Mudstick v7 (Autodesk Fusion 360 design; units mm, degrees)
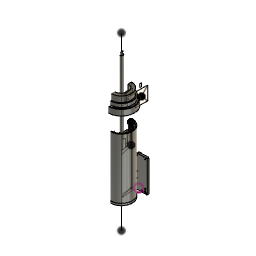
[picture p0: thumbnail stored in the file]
parameter "flexure_w" = 1.5
parameter "gap_w" = 1
parameter "t_sheet_main" = 6.6
parameter "t_sheet_second" = 3.175 (= "1 / 8 * 1")
parameter "tube_wallthick" = 3.3
parameter "tube_id" = 70
parameter "tube_len" = 210
parameter "id_bspushbearing" = 40
parameter "od_bspushbearing" = 52
parameter "t_bspushbearing" = 7
parameter "hw_m4insert_d" = 5.8
parameter "hw_m4insert_l" = 4.6
parameter "p_teeth" = 2
parameter "pd_pinion" = 12.7324 (= "p_teeth * nt_pinion / PI")
parameter "pd_driven" = 76.3944 (= "p_teeth * nt_driven / PI")
parameter "belt_length" = 280
parameter "c_dist_manuel" = 70.75
parameter "d101" = 7 (= "t_bspushbearing")
sketch "Sketch1" plane through (0, 0, 0) normal (0, 1, 0) x axis (1, 0, 0)
  line L1 (73.8, 0) -> (0, 0)
  line L2 (73.8, -110) -> (73.8, 0)
  line L3 (0, -110) -> (73.8, -110)
  line L4 (0, 0) -> (0, -110)
  line L5 (36.9, 0) -> (36.9, -110)
  line L6 (34.4, -109) -> (36.9, -109)
  line L7 (34.4, -101) -> (34.4, -109)
  line L8 (36.9, -101) -> (34.4, -101)
  line L9 (36.9, -45) -> (6.9, -5)
  line L10 (2.5, -3.3) -> (7.3, -9.7)
  line L11 (6.5, -0.3) -> (2.5, -3.3)
  line L12 (11.3, -6.7) -> (6.5, -0.3)
  line L13 (7.3, -9.7) -> (11.3, -6.7)
  line L14 (6.9, -5) -> (4.9, -6.5)
  circle C1 centre (6.9, -105) radius 2.1
  circle C2 centre (6.9, -15) radius 2.1
  circle C3 centre (16.9, -5) radius 2.1
  circle C4 centre (36.9, -55) radius 2.1
  circle C5 centre (36.9, -35) radius 2.1
  circle C6 centre (36.9, -45) radius 35.125
  circle C7 centre (6.9, -15) radius 4.1
  circle C8 centre (6.9, -105) radius 4.1
  circle C9 centre (16.9, -5) radius 4.1
  circle C10 centre (36.9, -55) radius 4.1
  circle C11 centre (36.9, -35) radius 4.1
  point P1 (0, 0)
  point P2 (0, 0)
  point P6 (36.9, -110)
  point P7 (36.9, 0)
  point P11 (36.9, -55)
  point P12 (36.9, -35)
  point P13 (36.9, -45)
  point P14 (36.9, -45)
  point P15 (36.9, -109)
  point P18 (36.9, -101)
  point P19 (34.4, -105)
  point P8 (6.9, -105)
  point P21 (36.9, -45)
  point P9 (6.9, -15)
  point P20 (6.9, -5)
  point P10 (16.9, -5)
  point P26 (9.3, -8.2)
  point P27 (4.9, -6.5)
  point P28 (6.9, -5)
  point P4 (73.8, -110)
  point P5 (0, -110)
  point P16 (34.4, -109)
  point P17 (34.4, -101)
  point P22 (7.3, -9.7)
  point P25 (11.3, -6.7)
  point P24 (6.5, -0.3)
  point P33 (36.9, -35)
  point P30 (6.9, -105)
  horizontal L1
  vertical L2
  horizontal L3
  coincident P1 P2
  midpoint L3 P6
  midpoint L1 P7
  equal C1 C2
  equal C1 C3
  coincident L5 P11
  coincident L5 P12
  equal C1 C4
  equal C1 C5
  coincident L5 P13
  coincident P13 P14
  coincident L5 P15
  perpendicular L5 L6
  perpendicular L6 L7
  perpendicular L5 L8
  coincident L5 P18
  midpoint L7 P19
  horizontal P8 P19
  coincident P14 P21
  vertical P9 P20
  horizontal P10 P20
  perpendicular L10 L11
  parallel L10 L12
  parallel L11 L13
  midpoint L13 P26
  coincident L9 P26
  midpoint L10 P27
  perpendicular L10 L14
  coincident P20 P28
  concentric C2 C7
  vertical L4
  perpendicular L9 L14
  concentric C1 C8
  concentric C3 C9
  equal C7 C9
  equal C7 C8
  concentric C4 C10
  concentric C5 C11
  equal C8 C10
  equal C8 C11
  dimension "d1" distance P4 P5 = 73.8
  dimension "d2" distance P2 P5 = 110
  dimension "d3" distance L5 P8 = 30
  dimension "d4" distance L3 P8 = 5
  dimension "d5" diameter C1 = 4.2
  dimension "d6" distance P11 P12 = 20
  dimension "d7" distance P8 P11 = 50
  dimension "d8" distance L1 P9 = 15
  dimension "d9" distance L1 P10 = 5
  dimension "d10" distance L5 P10 = 20
  dimension "d11" distance L5 P9 = 30
  dimension "d12" distance P12 P13 = 10
  dimension "d13" diameter C6 = 70.25
  dimension "d14" distance P15 P16 = 2.5
  dimension "d15" distance P16 P17 = 8
  dimension "d16" distance P22 P25 = 5
  dimension "d17" distance P24 P25 = 8
  dimension "d25" diameter C7 = 8.2
  dimension "d61" distance P10 P33 = 30
  dimension "d62" distance P9 P33 = 20
  dimension "d63" distance P30 P33 = 70
  dimension "d64" distance P8 P9 = 90
extrude "Extrude3" new body sketch "Sketch1" profile of L1 L3 L4 L5 C1 C2 C3 C4 C5 L6 L7 L8 L10 L11 L12 L13 C7 C8 C9 C10 C11 no distance stored bodies "Home Plate"
fillet "Fillet11" radius 1
mirror "Mirror3"
combine "Combine2"
work_plane "WorkPlane1"
sketch "Revolve" plane through (36.9, -3.3, 55) normal (-1, 0, 0) x axis (0, 1, 0)
  line L1 (-21.7, 45) -> (-18.4, 45)
  line L2 (-21.7, -165) -> (-21.7, 45)
  line L3 (-56.7, 45) -> (-21.7, 45)
  line L4 (-56.7, -445) -> (-56.7, 155)
  line L5 (-18.4, -165) -> (-18.4, 45)
  line L6 (-21.7, -165) -> (-18.4, -165)
  line L7 (-21.75, 45.05) -> (-18.4, 45.05)
  line L8 (-21.75, 40.05) -> (-21.75, 45.05)
  line L9 (-22.75, 40.05) -> (-21.75, 40.05)
  line L10 (-53.2, 51.1329) -> (-22.75, 40.05)
  line L11 (-53.2, 55.1329) -> (-53.2, 51.1329)
  line L12 (-18.4, 45.05) -> (-18.4, 52.0883)
  line L13 (-18.4, 52.0883) -> (-53.2, 55.1329)
  line L14 (-56.7, -75.8671) -> (-22.2, -85.1114)
  line L15 (-11.08, -225) -> (-30.7, -225)
  line L16 (-30.7, -230) -> (-30.7, -225)
  line L17 (-33.7, -233) -> (-30.7, -230)
  line L18 (-33.7, -237) -> (-33.7, -233)
  line L19 (-30.7, -240) -> (-33.7, -237)
  line L20 (-30.7, -245) -> (-30.7, -240)
  line L21 (-11.08, -245) -> (-30.7, -245)
  line L22 (-25.62, -238.4) -> (-25.62, -245)
  line L23 (-13.62, -238.4) -> (-25.62, -238.4)
  line L24 (-13.62, -245) -> (-13.62, -238.4)
  line L25 (-11.08, -225) -> (-11.08, -245)
  line L26 (-36.7, -243.7) -> (-35.4, -245)
  line L27 (-36.7, -229) -> (-36.7, -243.7)
  line L28 (-45.45, -229) -> (-36.7, -229)
  line L29 (-45.45, -258.5) -> (-45.45, -229)
  line L30 (-36.7, -226.3) -> (-36.7, -228.5)
  line L31 (-35.4, -225) -> (-36.7, -226.3)
  line L32 (-34.7, -225) -> (-35.4, -225)
  line L33 (-34.7, -222) -> (-34.7, -225)
  line L34 (-45.45, -222) -> (-34.7, -222)
  line L35 (-45.45, -228.5) -> (-45.45, -222)
  line L36 (-36.7, -228.5) -> (-45.45, -228.5)
  line L37 (-34.7, -245) -> (-35.4, -245)
  line L38 (-34.7, -246.5) -> (-34.7, -245)
  line L39 (-40.7, -258.5) -> (-40.7, -229)
  line L40 (-42.85, -236.35) -> (-42.85, -253.15)
  line L41 (-38.55, -258.5) -> (-38.55, -229)
  line L42 (-17.5028, -258.5) -> (-45.45, -258.5)
  line L43 (-40.7, -222) -> (-40.7, -228.5)
  line L44 (-42.85, -228.5) -> (-42.85, -222)
  line L45 (-17.5028, -246.5) -> (-34.7, -246.5)
  line L46 (-17.5028, -258.5) -> (-17.5028, -246.5)
  line L47 (-36.7, -232) -> (-32.7, -232)
  line L48 (7.6838, -246.5) -> (7.6838, -258.5)
  line L49 (14.05, -246.5) -> (7.6838, -246.5)
  line L50 (14.05, -258.5) -> (14.05, -246.5)
  line L51 (7.6838, -258.5) -> (14.05, -258.5)
  line L52 (35.2, -193) -> (-7.1, -193)
  line L53 (35.2, -241) -> (35.2, -193)
  line L54 (-7.1, -241) -> (35.2, -241)
  line L55 (-7.1, -193) -> (-7.1, -241)
  line L56 (35.2, -241) -> (-7.1, -193)
  line L57 (-7.1, -241) -> (35.2, -193)
  line L58 (-52.7, -89.8671) -> (-56.7, -89.8671)
  line L59 (-52.7, -104.8671) -> (-52.7, -89.8671)
  line L60 (-51.7, -104.8671) -> (-52.7, -104.8671)
  line L61 (-51.7, -143.8671) -> (-51.7, -104.8671)
  line L62 (-50.7, -143.8671) -> (-51.7, -143.8671)
  line L63 (-50.7, -379.8671) -> (-50.7, -143.8671)
  line L64 (-52.7, -379.8671) -> (-50.7, -379.8671)
  line L65 (-52.7, -389.8671) -> (-52.7, -379.8671)
  line L66 (-56.7, -389.8671) -> (-52.7, -389.8671)
  line L67 (-21.5028, -278.5) -> (-21.5028, -258.5)
  line L68 (-33.5028, -278.5) -> (-21.5028, -278.5)
  line L69 (-33.5028, -258.5) -> (-33.5028, -278.5)
  line L70 (-26.24, -104.7344) -> (-26.24, -160.8276)
  line L71 (-35.7725, -102.1801) -> (-26.24, -104.7344)
  line L72 (-36.7, -91.5789) -> (-35.7725, -102.1801)
  line L73 (-56.7, -86.2199) -> (-36.7, -91.5789)
  line L74 (-26.24, -160.8276) -> (-22.2, -160.8276)
  line L75 (-30.6415, -160.8276) -> (-35.7725, -102.1801)
  line L76 (-26.24, -160.8276) -> (-30.6415, -160.8276)
  line L77 (-51.45, -141.6671) -> (-51.45, -119.0671)
  line L78 (-35.9267, -141.6671) -> (-51.45, -141.6671)
  line L79 (-36.8449, -91.6436) -> (-35.9267, -102.1388)
  line L80 (-42.5953, -90.1027) -> (-36.8449, -91.6436)
  line L81 (-42.5953, -119.0671) -> (-42.5953, -90.1027)
  line L82 (-51.45, -119.0671) -> (-42.5953, -119.0671)
  line L83 (-35.9267, -141.6671) -> (-35.9267, -102.1388)
  line L84 (-42.5953, -100.352) -> (-35.9267, -102.1388)
  line L85 (-35.9267, -102.1388) -> (-35.7725, -102.1801)
  line L86 (-42.5953, -89.9992) -> (-42.5953, -90.1027)
  line L87 (-22.2, -88.8276) -> (-22.8081, -88.8276)
  line L88 (-22.2, -85.1114) -> (-22.2, -86.1114)
  line L89 (-23.7, -92.3276) -> (-22.2, -90.8276)
  line L90 (-23.7, -153.6114) -> (-23.7, -92.3276)
  line L91 (-22.8081, -158.8276) -> (-22.2, -158.8276)
  line L92 (-22.2, -155.1114) -> (-22.2, -156.1114)
  line L93 (-23.7, -153.6114) -> (-22.2, -155.1114)
  line L94 (-22.2, -86.1114) -> (-22.8081, -86.1114)
  line L95 (-22.2, -156.1114) -> (-22.8081, -156.1114)
  line L96 (-22.2, -156.1114) -> (-22.2, -88.8276)
  line L97 (-22.2, -160.8276) -> (-22.2, -156.1114)
  line L98 (-43.6, -253.9) -> (-42.85, -253.15)
  line L99 (-43.6, -258.5) -> (-43.6, -253.9)
  line L100 (-43.6, -235.6) -> (-42.85, -236.35)
  line L101 (-43.6, -229) -> (-43.6, -235.6)
  line L102 (-35.7, -214) -> (-35.7, -222)
  line L103 (-50.7, -214) -> (-35.7, -214)
  circle C1 centre (-22.8081, -87.4695) radius 1.3081
  arc A1 centre (-22.8081, -87.4695) radius 1.3581 clockwise from (-22.8081, -88.8276) to (-22.8081, -86.1114)
  circle C2 centre (-22.8081, -157.4695) radius 1.3081
  arc A2 centre (-22.8081, -157.4695) radius 1.3581 clockwise from (-22.8081, -158.8276) to (-22.8081, -156.1114)
  point P4 (-21.7, -165)
  point P10 (-21.7, -165)
  point P5 (-56.7, 45)
  point P11 (-18.4, 45.05)
  point P18 (-18.4, 45.05)
  point P2 (-18.4, 45)
  point P16 (-53.2, 55.1329)
  point P19 (-53.2, 55.1329)
  point P21 (-56.7, -75.8671)
  point P28 (-30.7, -240)
  point P31 (-25.62, -245)
  point P34 (-13.62, -245)
  point P24 (-11.08, -225)
  point P35 (-11.08, -225)
  point P41 (-36.7, -228.5)
  point P48 (-36.7, -228.5)
  point P39 (-45.45, -229)
  point P51 (-40.7, -229)
  point P53 (-38.55, -229)
  point P23 (-30.7, -225)
  point P52 (-40.7, -258.5)
  point P54 (-38.55, -258.5)
  point P29 (-30.7, -245)
  point P44 (-34.7, -225)
  point P56 (-40.7, -228.5)
  point P57 (-40.7, -222)
  point P59 (-42.85, -228.5)
  point P62 (-32.7, -232)
  point P63 (-36.7, -232)
  point P64 (7.6838, -258.5)
  point P68 (7.6838, -258.5)
  point P73 (14.05, -217)
  point P66 (14.05, -246.5)
  point P61 (-17.5028, -258.5)
  point P60 (-17.5028, -246.5)
  point P74 (-56.7, -89.8671)
  point P83 (-56.7, -389.8671)
  point P92 (-56.7, -86.2199)
  point P88 (-26.24, -160.8276)
  point P93 (-26.24, -160.8276)
  point P94 (-51.45, -119.0671)
  point P99 (-51.45, -119.0671)
  point P101 (-30.6415, -160.8276)
  point P102 (-30.6415, -160.8276)
  point P103 (-35.9267, -102.1388)
  point P105 (-42.5953, -100.352)
  point P100 (-35.9267, -141.6671)
  point P104 (-35.9267, -141.6671)
  point P106 (-42.5953, -89.9992)
  point P108 (-21.5, -87.4695)
  point P107 (-22.8081, -87.4695)
  point P109 (-22.8081, -87.4695)
  point P20 (-22.2, -85.1114)
  point P112 (-22.2, -85.1114)
  point P113 (-22.2, -90.8276)
  point P116 (-22.8081, -157.4695)
  point P117 (-22.2, -158.8276)
  point P119 (-22.8081, -157.4695)
  point P115 (-23.7, -153.6114)
  point P121 (-23.7, -153.6114)
  point P111 (-22.2, -88.8276)
  point P125 (-22.2, -156.1114)
  point P58 (-42.85, -222)
  point P55 (-17.5028, -258.5)
  point P84 (-21.5028, -258.5)
  point P87 (-33.5028, -258.5)
  point P128 (-43.6, -258.5)
  point P131 (-43.6, -229)
  point P129 (-42.85, -236.35)
  point P132 (-35.7, -222)
  point P134 (-50.7, -214)
  point P8 (3.3, 55)
  point P3 (-21.7, 45)
  point P6 (-56.7, 155)
  point P7 (-56.7, -445)
  point P12 (-21.75, 45.05)
  point P13 (-21.75, 40.05)
  point P14 (-22.75, 40.05)
  point P15 (-53.2, 51.1329)
  point P33 (-13.62, -238.4)
  point P32 (-25.62, -238.4)
  point P30 (-11.08, -245)
  point P42 (-36.7, -226.3)
  point P49 (-34.7, -245)
  point P50 (-34.7, -246.5)
  point P45 (-34.7, -222)
  point P37 (-36.7, -243.7)
  point P67 (14.05, -258.5)
  point P71 (35.2, -241)
  point P72 (-7.1, -241)
  point P70 (35.2, -193)
  point P81 (-52.7, -379.8671)
  point P82 (-52.7, -389.8671)
  point P75 (-52.7, -89.8671)
  point P76 (-52.7, -104.8671)
  point P77 (-51.7, -104.8671)
  point P78 (-51.7, -143.8671)
  point P85 (-21.5028, -278.5)
  point P86 (-33.5028, -278.5)
  point P79 (-50.7, -143.8671)
  point P91 (-36.7, -91.5789)
  point P120 (-22.2, -155.1114)
  point P123 (-22.2, -86.1114)
  point P46 (-45.45, -222)
  point P127 (-43.6, -253.9)
  point P130 (-43.6, -235.6)
  point P133 (-35.7, -214)
  horizontal L1
  perpendicular L1 L2
  perpendicular L2 L3
  vertical L4
  perpendicular L3 L5
  perpendicular L5 L6
  coincident P4 P10
  coincident P5 L4
  perpendicular L2 L7
  perpendicular L3 L8
  perpendicular L8 L9
  perpendicular L3 L11
  parallel L11 L12
  coincident P11 P18
  coincident P2 L12
  coincident P16 P19
  coincident L4 P21
  perpendicular L74 L96
  horizontal L15
  perpendicular L15 L16
  perpendicular L15 L18
  perpendicular L17 L19
  perpendicular L18 L21
  vertical L20
  equal L16 L20
  coincident L16 P28
  coincident L21 P31
  perpendicular L21 L22
  perpendicular L22 L23
  coincident L21 P34
  perpendicular L21 L24
  perpendicular L21 L25
  coincident P24 P35
  vertical L27
  perpendicular L27 L28
  perpendicular L28 L29
  perpendicular L28 L30
  perpendicular L30 L32
  perpendicular L32 L33
  perpendicular L33 L34
  perpendicular L34 L35
  perpendicular L35 L36
  coincident P41 P48
  coincident L27 P48
  coincident P39 L35
  horizontal L37
  perpendicular L37 L38
  coincident L28 P51
  perpendicular L28 L39
  perpendicular L28 L40
  coincident L28 P53
  perpendicular L28 L41
  coincident P23 L32
  perpendicular L29 L42
  coincident P52 L42
  coincident P54 L42
  coincident P29 L37
  coincident P44 L38
  coincident L36 P56
  coincident L34 P57
  perpendicular L34 L43
  coincident P51 L43
  coincident L36 P59
  perpendicular L36 L44
  perpendicular L38 L45
  perpendicular L45 L46
  coincident L17 P62
  coincident L27 P63
  perpendicular L27 L47
  vertical L48
  perpendicular L48 L49
  perpendicular L49 L50
  perpendicular L50 L51
  coincident P64 P68
  perpendicular L52 L53
  parallel L52 L54
  parallel L53 L55
  horizontal L52
  coincident L56 P73
  coincident L57 P73
  vertical P66 P73
  coincident P61 L51
  coincident P60 L49
  coincident L4 P74
  perpendicular L4 L58
  perpendicular L58 L59
  perpendicular L4 L60
  perpendicular L60 L61
  perpendicular L4 L62
  perpendicular L62 L63
  perpendicular L63 L64
  perpendicular L64 L65
  coincident L4 P83
  perpendicular L4 L66
  perpendicular L67 L68
  perpendicular L70 L74
  coincident L4 P92
  parallel L71 L73
  parallel L14 L71
  coincident P88 P93
  vertical L77
  perpendicular L78 L81
  coincident P94 P99
  parallel L73 L80
  parallel L72 L75
  coincident P101 P102
  horizontal L76
  parallel L75 L79
  coincident L71 P103
  coincident L81 P105
  collinear L71 L84
  horizontal L82
  coincident P100 P104
  vertical L83
  coincident L73 P106
  parallel L81 L86
  coincident C1 P108
  horizontal P107 P108
  vertical L96
  coincident P107 P109
  horizontal L87
  vertical L88
  coincident P20 P112
  tangent A1 L87
  coincident P113 L96
  vertical L90
  vertical P107 P116
  equal C1 C2
  coincident P117 L96
  perpendicular L91 L96
  coincident P116 P119
  tangent L91 A2
  vertical L92
  coincident P115 P121
  coincident P111 L88
  tangent A1 L94
  horizontal L94
  tangent A2 L95
  coincident L92 P125
  horizontal L95
  collinear L96 L97
  coincident L34 P58
  coincident P55 P61
  vertical L69
  vertical L67
  coincident L42 P84
  coincident L42 P87
  coincident L42 P128
  perpendicular L42 L99
  coincident L28 P131
  perpendicular L28 L101
  coincident L44 P129
  coincident L34 P132
  perpendicular L34 L102
  coincident L63 P134
  perpendicular L63 L103
  dimension "d75" distance L4 P8 = 60
  dimension "d76" distance P2 P3 = 3.3 (= "tube_wallthick")
  dimension "d80" distance L2 L4 = 35 (= "tube_id / 2")
  dimension "d81" distance P3 P4 = 210 (= "tube_len")
  dimension "d82" distance L3 P8 = 10
  dimension "d83" distance P6 P8 = 100
  dimension "d84" distance P7 P8 = 500
  dimension "d85" distance L1 L7 = 0.05
  dimension "d86" distance P12 P13 = 5
  dimension "d87" distance L2 L8 = 0.05
  dimension "d88" distance P13 P14 = 1
  dimension "d89" angle L10 L11 = 70
  dimension "d90" distance P15 P16 = 4
  dimension "d92" angle L11 L13 = 85
  dimension "d93" distance L4 L11 = 3.5
  dimension "d96" angle L10 L14 = 5
  dimension "d103" angle L18 L19 = 45
  dimension "d105" distance P28 P29 = 5
  dimension "d106" distance L4 L20 = 26 (= "od_bspushbearing / 2")
  dimension "d107" distance P33 P34 = 6.6 (= "t_sheet_main")
  dimension "d108" distance P32 P33 = 12
  dimension "d110" distance L20 L22 = 5.08 (= "2.54 mm * 2")
  dimension "d111" distance P4 P23 = 60
  dimension "d112" distance P30 P35 = 20
  dimension "d113" distance L18 P28 = 3
  dimension "d114" distance L28 L36 = 0.5
  dimension "d115" distance L4 L29 = 11.25 (= "( 22 / 2 ) * 1 mm + 0.25 mm")
  dimension "d116" distance L4 L27 = 20 (= "id_bspushbearing / 2")
  dimension "d117" distance L4 L39 = 16 (= "( 32 / 2 ) * 1 mm")
  dimension "d118" distance L39 L40 = 2.15 (= "( 4.3 / 2 ) * 1 mm")
  dimension "d119" distance L39 L41 = 2.15 (= "d118")
  dimension "d120" angle L31 L32 = 45
  dimension "d121" distance P42 L32 = 1.3
  dimension "d122" distance L30 L33 = 2
  dimension "d125" distance P49 P50 = 1.5
  dimension "d127" distance P44 P45 = 3
  dimension "d129" angle L26 L27 = 45
  dimension "d130" distance P37 L37 = 1.3 (= "d121")
  dimension "d146" distance L4 L46 = 39.1972 (= "pd_driven / 2 + 1 mm")
  dimension "d149" distance P60 P61 = 12
  dimension "d150" distance P23 L47 = 7 (= "t_bspushbearing")
  dimension "d151" distance P67 P68 = 6.3662 (= "pd_pinion / 2")
  dimension "d152" distance L4 L50 = 70.75 (= "c_dist_manuel")
  dimension "d153" distance P71 P72 = 42.3
  dimension "d154" distance P70 P71 = 48
  dimension "d155" distance P30 L54 = 4
  dimension "d156" distance P33 L25 = 2.54
  dimension "d157" distance P15 P21 = 127 (= "5")
  dimension "d158" distance P81 P82 = 10
  dimension "d159" distance P82 P83 = 4 (= "( 8 / 2 ) * 1 mm")
  dimension "d160" distance L4 L63 = 6 (= "( 12 / 2 ) * 1 mm")
  dimension "d161" distance P74 P75 = 4 (= "( 8 / 2 ) * 1 mm")
  dimension "d162" distance P75 P76 = 15
  dimension "d163" distance L4 L61 = 5 (= "( 10 / 2 ) * 1 mm")
  dimension "d164" distance P77 P78 = 39
  dimension "d165" distance P74 P83 = 300
  dimension "d166" distance P21 P74 = 14
  dimension "d168" distance P84 P85 = 20
  dimension "d169" distance P61 L67 = 4
  dimension "d170" distance P85 P86 = 12
  dimension "d173" distance L14 L73 = 10
  dimension "d176" distance L61 L77 = 0.25
  dimension "d177" distance P79 L78 = 2.2
  dimension "d179" distance L4 L81 = 14.1047 (= "61 / 64 * 1  / 2 + 2 mm")
  dimension "d180" distance P77 L82 = 14.2 (= "10 mm + 2.2 mm + 2 mm")
  dimension "d181" distance L73 L80 = 0.1
  dimension "d185" distance L4 P91 = 20
  dimension "d186" angle L72 L96 = 5
  dimension "d187" distance L75 L79 = 0.15
  dimension "d188" distance L71 L73 = 10
  dimension "d211" = 71.8919
  dimension "d214" diameter C1 = 2.6162
  dimension "d216" distance L2 P108 = 0.2
  dimension "d217" distance C1 A1 = 0.05
  dimension "d220" distance L2 L96 = 0.5
  dimension "d221" angle L89 L96 = 45
  dimension "d222" distance P111 P113 = 2
  dimension "d223" distance L2 L90 = 2
  dimension "d224" distance L70 L90 = 2.54
  dimension "d225" distance L74 P117 = 2
  dimension "d226" distance C2 A2 = 0.05
  dimension "d227" distance P107 P119 = 70 (= "tube_id")
  dimension "d228" angle L92 L93 = 45
  dimension "d229" distance P120 P125 = 1
  dimension "d230" distance P112 P123 = 1
  dimension "d232" = 25.7733
  dimension "d234" distance L4 P61 = 39.1972
  dimension "d235" distance P46 L42 = 36.5
  dimension "d237" distance L39 L99 = 2.9 (= "hw_m4insert_d / 2")
  dimension "d238" distance P127 P128 = 4.6 (= "hw_m4insert_l")
  dimension "d239" angle L98 L99 = 45
  dimension "d240" distance P23 L28 = 4
  dimension "d241" distance L39 L101 = 2.9 (= "hw_m4insert_d / 2")
  dimension "d242" distance P130 P131 = 6.6 (= "hw_m4insert_l + 2 mm")
  dimension "d243" angle L100 L101 = 45
  dimension "d246" distance L4 P45 = 22
  dimension "d247" distance L4 L102 = 21 (= "( 42 / 2 ) * 1 mm")
  dimension "d248" distance P132 P133 = 8
  dimension "d249" = 63.2612
  dimension "d250" = 128.2388
  dimension "d251" = 12.7867
revolve "Revolve1" sketch "Revolve" AlongAngle 360 bodies "Canister"
revolve "Revolve2" sketch "Revolve" AlongAngle 36 (= "( 360 / 10 ) * 1 deg") AgainstAngle 36 (= "( 360 / 10 ) * 1 deg")
chamfer "Chamfer3" distance 9.9 distance 6
revolve "Revolve3" sketch "Revolve" AlongAngle 360
circular_pattern "C-Pattern1" TotalAngle 360
combine "Combine3"
combine "Combine4"
fillet "Fillet12" radius 2
fillet "Fillet13" radius 2
fillet "Fillet14" radius 2
fillet "Fillet15" radius 2
fillet "Fillet16" radius 2
combine "Combine5"
fillet "Fillet17" radius 2
fillet "Fillet18" radius 2
chamfer "Chamfer4" distance 1
chamfer "Chamfer5" distance 1
fillet "Fillet19" radius 2
revolve "Revolve4" sketch "Revolve" AlongAngle 2.6 AgainstAngle 2.6
fillet "Fillet20" radius 2
circular_pattern "C-Pattern2" countU 10 TotalAngle 360
fillet "Fillet21" radius 1
revolve "Revolve5" sketch "Revolve" AlongAngle 360
chamfer "Chamfer6" distance 0.5
circular_pattern "C-Pattern3" TotalAngle 360
named bodies: "Home Plate", "Canister", "Inner Plunger", "Outer Plunger"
